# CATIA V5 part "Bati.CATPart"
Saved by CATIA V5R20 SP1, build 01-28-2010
Part number: Bati
Bounding box of the stored display mesh (mm): x -80 to 80, y -30 to 30, z 0 to 75
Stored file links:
  E:\EDELI\gcausse\Edeli_2012_184_gcausse\Bati.CATPart
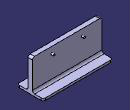
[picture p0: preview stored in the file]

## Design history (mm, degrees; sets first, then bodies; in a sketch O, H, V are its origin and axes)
Body1 (main body)
  Sketch1 on xy-plane, origin (0, 0, 0), H (1, 0, 0), V (0, 1, 0)
    line L1 (-80, 30) -> (80, 30)
    line L2 (80, 30) -> (80, -30)
    line L3 (80, -30) -> (-80, -30)
    line L4 (-80, -30) -> (-80, 30)
    horizontal: L1 H, L3 H
    vertical: L2 V, L4 V
  Pad1: profile Sketch1, direction (0, 0, 1), length 5
  Sketch2 on end face of Pad1, origin (0, 0, 5), H (1, 0, 0), V (0, 1, 0)
    line L1 (-80, 5) -> (80, 5)
    line L2 (80, 5) -> (80, -5)
    line L3 (80, -5) -> (-80, -5)
    line L4 (-80, -5) -> (-80, 5)
    reference projected line E1 (-80, -30) -> (80, -30) from edge [face of Pad1 from Sketch1.L3 | end face of Pad1]
    distance E1 L1 = 35
    distance L3 L1 = 10
    horizontal: L1 H, L3 H
    vertical: L2 V, L4 V
  Pad2: profile Sketch2, direction (0, 0, 1), length 70
  Fillet1: radius 5, on edge [end face of Pad1 | face of Pad2 from Sketch2.L1]; edge [end face of Pad1 | face of Pad2 from Sketch2.L3]; edge [face of Pad1 from Sketch1.L3 | face of Pad2]; edge [face of Pad2 | face of Pad1 from Sketch1.L3]; edge [face of Pad1 from Sketch1.L1 | face of Pad2]; edge [face of Pad2 | face of Pad1 from Sketch1.L1]
  Fillet2: radius 5, on edge [face of Pad2 | end face of Pad2] (x2)
  Sketch3 on face of Pad2 from Sketch2.L1, origin (0, 5, 0), H (-1, 0, 0), V (0, 0, 1)
    circle A1 centre (-35, 60) radius 2.5
    point P1 (-35, 60)
    circle A2 centre (35, 60) radius 2.5
    point P2 (35, 60)
    reference projected line E1 (-80, 5) -> (-80, 75) from edge [face of Pad2 from Sketch2.L1 | face of Pad2]
    radius A2 = 2.5
    radius A1 = 2.5
    distance P1 P2 = 70
    distance E1 P1 = 45
  Pad3: profile Sketch3, direction (0, 1, 0), length 5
